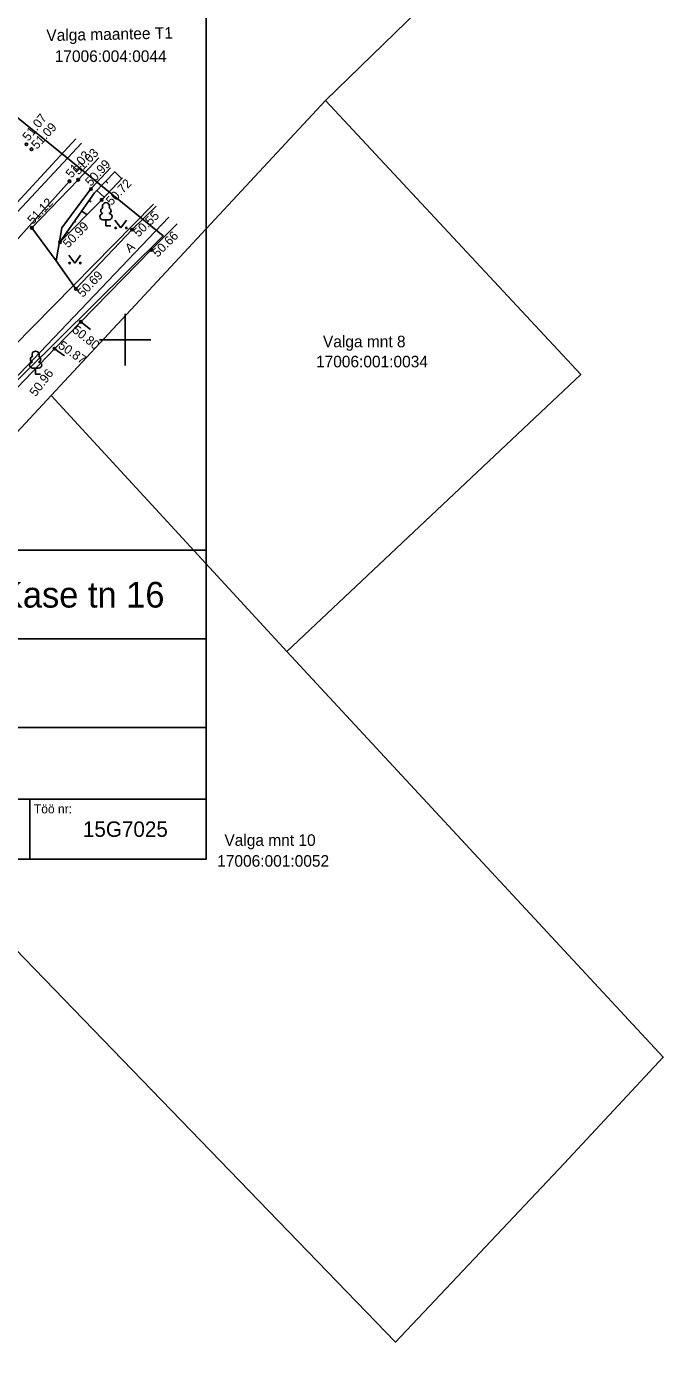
# Model space of a CAD drawing. Extents: x 640876 to 641418, y 6455595 to 6456085.
# Drawn here: x 641242.4 to 641291.8, y 6455670.3 to 6455774.3 of the extents above; entities that cross this region are included whole.
import ezdxf

# ---------------------------------------------------------------- set-up
doc = ezdxf.new("R2010")
doc.units = 0
for name, color, linetype in [('HALJASTUS', 7, 'Continuous'), ('KORGUS', 7, 'Continuous'), ('KTRASS', 7, 'Continuous'), ('MOOTPIIR', 7, 'Continuous'), ('PIIR', 7, 'Continuous'), ('PUU', 7, 'Continuous'), ('RELJEEF', 7, 'Continuous'), ('SITRASS', 7, 'Continuous'), ('TEE', 7, 'Continuous'), ('VORK', 7, 'Continuous'), ('VORMISTUS', 7, 'Continuous'), ('VTRASS', 7, 'Continuous')]:
    doc.layers.add(name, color=color, linetype=linetype)

msp = doc.modelspace()

# ---------------------------------------------------------------- linework, layer by layer
at = {"layer": 'HALJASTUS'}
for p, q in [((641249.21, 6455759.3), (641249.67, 6455758.69)), ((641249.67, 6455758.69), (641250.12, 6455759.3)), ((641245.62, 6455756.57), (641246.09, 6455755.96)), ((641246.09, 6455755.96), (641246.53, 6455756.57))]:
    msp.add_line(p, q, dxfattribs=at)
for centre in [(641249.27, 6455758.69), (641250.1, 6455758.69), (641245.69, 6455755.96), (641246.52, 6455755.96)]:
    msp.add_circle(centre, 0.055, dxfattribs=at)
at = {"layer": 'KORGUS'}
for centre in [(641242.33, 6455765.19), (641242.72, 6455764.81), (641245.68, 6455762.32), (641246.35, 6455762.44), (641247.35, 6455761.72), (641248.18, 6455760.88), (641242.75, 6455758.7), (641250.55, 6455758.56), (641244.94, 6455757.58), (641252.04, 6455756.99), (641246.18, 6455753.95), (641246.56, 6455751.39), (641244.52, 6455749.3)]:
    msp.add_circle(centre, 0.1, dxfattribs=at)
at = {"layer": 'KTRASS'}
msp.add_lwpolyline([(641230.6, 6455748.74), (641246.18, 6455765.63)], dxfattribs=at)
at = {"layer": 'MOOTPIIR'}
msp.add_lwpolyline([(641060.92, 6455895.94), (641100.06, 6455950.48), (641099.59, 6455952.16), (641069.13, 6455984.04), (641066.13, 6455988.62), (641076.46, 6456005.05), (641230.64, 6456010.05), (641237.36, 6455995.24), (641237.24, 6455992.81), (641236.26, 6455990.89), (641229.04, 6455971.32), (641203.03, 6455909.57), (641225.26, 6455906.85), (641239.51, 6455898.49), (641200.19, 6455851.7), (641192.02, 6455859.1), (641169.79, 6455829.14), (641192.02, 6455807.57), (641252.96, 6455758.07), (641231.39, 6455736.74), (641191.47, 6455775.98), (641152.42, 6455787.91), (641136.35, 6455788.31), (641049.07, 6455856.04)], dxfattribs=at)
at = {"layer": 'PIIR'}
msp.add_lwpolyline([(641274.59, 6455777.38), (641265.59, 6455768.59), (641244.26, 6455745.67), (641222.48, 6455722.23), (641201.2, 6455700.54), (641180.13, 6455678.32), (641171.14, 6455668.19), (641142.12, 6455638.98), (641132.03, 6455627.4), (641101.1, 6455594.76), (641087.79, 6455611.35), (641100.72, 6455625.11), (641099.2, 6455626.54), (641113.86, 6455642.06), (641121.21, 6455649.84), (641140.58, 6455669.91), (641170.91, 6455704.35), (641182.28, 6455716.38), (641216.67, 6455752.61), (641234.69, 6455771.62), (641250.06, 6455787.79)], dxfattribs=at)
for points in [[(641262.56, 6455725.76), (641244.26, 6455745.67), (641265.59, 6455768.59), (641285.42, 6455747.29)], [(641244.26, 6455745.67), (641262.56, 6455725.76), (641276.8, 6455710.41), (641291.83, 6455694.21), (641284.13, 6455685.93), (641271.03, 6455672.05), (641222.48, 6455722.23)]]:
    msp.add_lwpolyline(points, close=True, dxfattribs=at)
at = {"layer": 'PUU'}
for p, q in [((641248.75, 6455759.33), (641248.27, 6455759.33)), ((641248.51, 6455758.86), (641248.51, 6455759.33)), ((641248.89, 6455758.86), (641248.51, 6455758.86)), ((641243.28, 6455747.79), (641242.8, 6455747.79)), ((641243.04, 6455747.31), (641243.04, 6455747.79)), ((641243.42, 6455747.31), (641243.04, 6455747.31))]:
    msp.add_line(p, q, dxfattribs=at)
for centre, radius, start, end in [((641248.34, 6455760.03), 0.233, 109.0217, 253.1415), ((641248.51, 6455760.38), 0.277, 332.5799, 207.4201), ((641248.68, 6455760.03), 0.233, 286.8508, 70.9859), ((641248.27, 6455759.57), 0.238, 90.0016, 269.3953), ((641248.75, 6455759.57), 0.238, 270.6047, 89.9984), ((641243.04, 6455748.83), 0.277, 332.5799, 207.4201), ((641242.81, 6455748.02), 0.238, 90.0016, 269.3953), ((641242.87, 6455748.48), 0.233, 109.0217, 253.1415), ((641243.21, 6455748.48), 0.233, 286.8508, 70.9859), ((641243.28, 6455748.02), 0.238, 270.6047, 89.9984)]:
    msp.add_arc(centre, radius, start, end, dxfattribs=at)
at = {"layer": 'RELJEEF'}
for p, q in [((641248.5, 6455762.33), (641248.67, 6455762.17)), ((641249.2, 6455763.05), (641249.75, 6455762.52)), ((641247.81, 6455761.61), (641248.37, 6455761.08)), ((641247.2, 6455760.82), (641247.37, 6455760.71)), ((641246.06, 6455759.18), (641246.14, 6455759.13)), ((641246.63, 6455760), (641247.04, 6455759.72)), ((641245.49, 6455758.36), (641245.62, 6455758.27))]:
    msp.add_line(p, q, dxfattribs=at)
for points in [[(641249.22, 6455763.08), (641247.62, 6455761.42), (641244.94, 6455757.58)], [(641249.81, 6455762.58), (641248.18, 6455760.88), (641244.94, 6455757.58)]]:
    msp.add_lwpolyline(points, dxfattribs=at)
at = {"layer": 'SITRASS'}
for points in [[(641236.64, 6455744.74), (641252.22, 6455760.55)], [(641230.72, 6455735.76), (641253.41, 6455759.54)]]:
    msp.add_lwpolyline(points, dxfattribs=at)
at = {"layer": 'TEE'}
for points in [[(641247.95, 6455764.14), (641246.35, 6455762.44), (641242.75, 6455758.7), (641244.65, 6455756.13), (641246.18, 6455753.95)], [(641248.87, 6455763.37), (641247.35, 6455761.72), (641245.08, 6455758.7), (641244.65, 6455756.13)], [(641245.68, 6455762.32), (641239, 6455754.88), (641231.44, 6455746.49), (641225.91, 6455740.42)], [(641252.41, 6455760.39), (641250.55, 6455758.56), (641246.18, 6455753.95)], [(641254.06, 6455759), (641252.04, 6455756.99), (641246.56, 6455751.39), (641244.52, 6455749.3)], [(641246.56, 6455751.39), (641247.32, 6455750.79)], [(641231.14, 6455735.35), (641244.52, 6455749.3)], [(641245.3, 6455748.75), (641244.52, 6455749.3)]]:
    msp.add_lwpolyline(points, dxfattribs=at)
at = {"layer": 'VORK'}
for p, q in [((641250, 6455752), (641250, 6455748)), ((641248, 6455750), (641252, 6455750))]:
    msp.add_line(p, q, dxfattribs=at)
at = {"layer": 'VORMISTUS'}
for p, q in [((641256.3, 6455709.6), (641256.3, 6456020.09)), ((641256.3, 6455733.64), (641167.3, 6455733.64)), ((641256.3, 6455733.64), (641256.3, 6455709.6)), ((641256.3, 6455709.6), (641256.3, 6455733.64)), ((641203.73, 6455726.74), (641256.3, 6455726.74)), ((641167.3, 6455719.84), (641256.3, 6455719.84)), ((641203.73, 6455714.27), (641256.3, 6455714.27)), ((641242.6, 6455709.6), (641242.6, 6455714.27)), ((641035.12, 6455709.6), (641256.3, 6455709.6)), ((641167.3, 6455709.6), (641256.3, 6455709.6))]:
    msp.add_line(p, q, dxfattribs=at)
msp.add_lwpolyline([(641167.3, 6455733.64), (641256.3, 6455733.64), (641256.3, 6455709.6), (641167.3, 6455709.6)], close=True, dxfattribs=at)
at = {"layer": 'VTRASS'}
msp.add_lwpolyline([(641230.82, 6455748.15), (641239.84, 6455758.04), (641246.6, 6455765.28)], dxfattribs=at)

# ---------------------------------------------------------------- texts
at = {"layer": 'KORGUS'}
for s, rotation, p in [(' 51.07', 51.1443, (641242.33, 6455765.19)), (' 51.09', 47.2622, (641242.97, 6455764.57)), (' 51.02', 50.2219, (641245.68, 6455762.32)), (' 51.03', 46.5784, (641246.2, 6455762.58)), (' 50.99', 47.6369, (641247.16, 6455761.69)), (' 50.72', 46.2866, (641248.76, 6455760.21)), (' 51.12', 46.1545, (641242.65, 6455758.73)), (' 50.99', 45.5435, (641245.4, 6455756.9)), (' 50.55', 44.6205, (641250.86, 6455757.75)), (' 50.66', 44.8361, (641252.35, 6455756.18)), (' 50.69', 46.5568, (641246.54, 6455753.06)), (' 50.80', 321.6495, (641245.63, 6455750.8)), (' 50.87', 325.0731, (641244.53, 6455749.55)), (' 50.96', 52.6052, (641242.9, 6455745.32))]:
    msp.add_text(s, height=0.7, rotation=rotation, dxfattribs=at).set_placement(p)
at = {"layer": 'PIIR'}
for s, rotation, p in [('Valga maantee T1', 1.1484, (641243.89, 6455773.22)), ('17006:001:0034', 360, (641264.84, 6455747.85))]:
    msp.add_text(s, height=0.9, rotation=rotation, dxfattribs=at).set_placement(p)
for s, p in [('17006:004:0044', (641244.53, 6455771.6)), ('Valga mnt 8', (641265.38, 6455749.41)), ('Valga mnt 10', (641257.72, 6455710.64)), ('17006:001:0052', (641257.16, 6455709.02))]:
    msp.add_text(s, height=0.9, dxfattribs=at).set_placement(p)
at = {"layer": 'TEE'}
msp.add_text('A', height=0.7, rotation=39.0355, dxfattribs=at).set_placement((641250.35, 6455756.72))
at = {"layer": 'VORMISTUS'}
for s, height, p in [('Elva linn, Valga mnt 7a; 7c ja Kase tn 16', 2, (641205.04, 6455729.17)), ('Töö nr:', 0.7, (641242.91, 6455713.17)), ('15G7025', 1.2, (641246.72, 6455711.34))]:
    msp.add_text(s, height=height, dxfattribs=at).set_placement(p)

doc.saveas('drawing.dxf')
